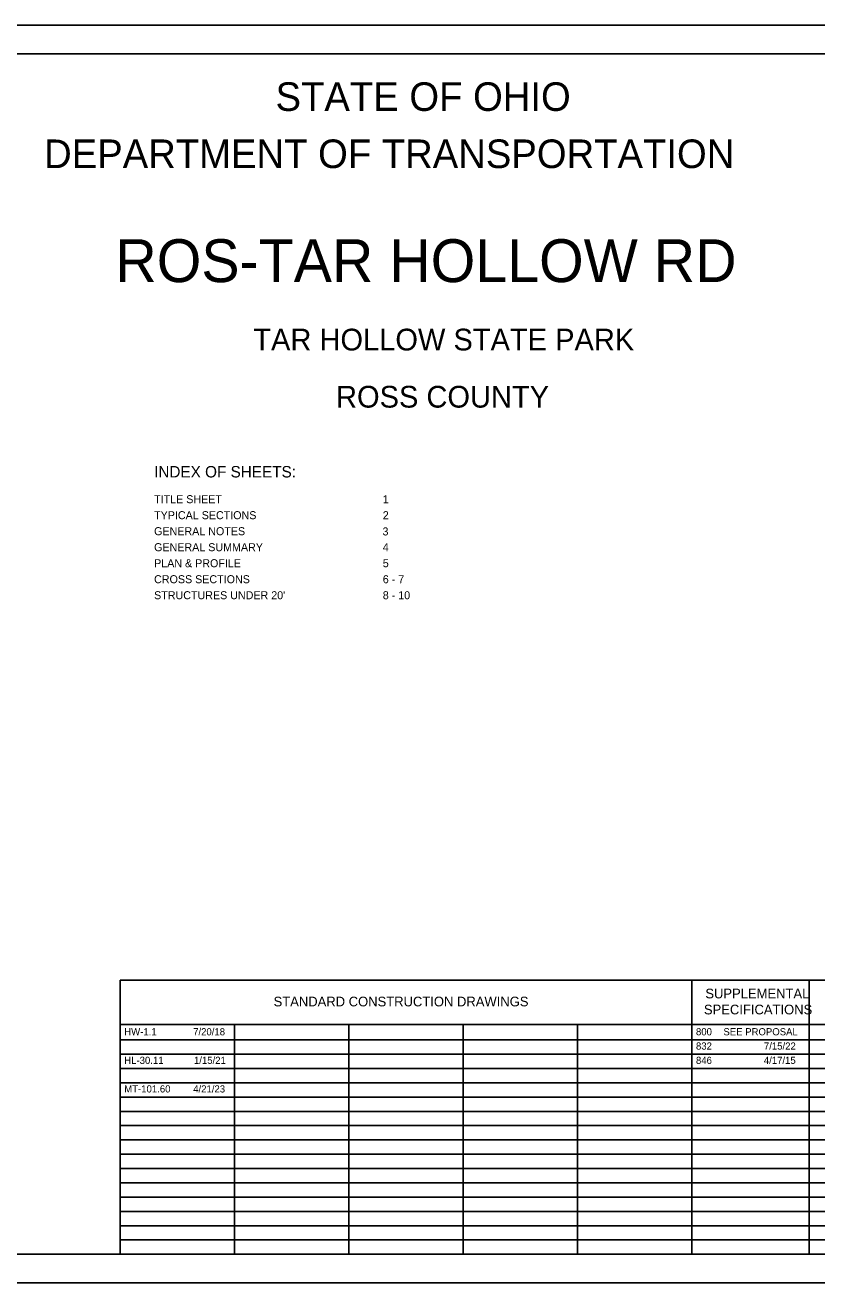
# Model space of a CAD drawing. Extents: x -13.1 to 43.1, y 0 to 22.
# Drawn here: x 9.59 to 23.44, y 0 to 22 of the extents above; entities that cross this region are included whole.
import ezdxf

# ---------------------------------------------------------------- set-up
doc = ezdxf.new("R2010")
doc.units = 0
for name, color, linetype in [('SH_Border', 7, 'Continuous'), ('SH_Data', 7, 'Continuous'), ('SH_Text', 7, 'Continuous')]:
    doc.layers.add(name, color=color, linetype=linetype)

msp = doc.modelspace()

# ---------------------------------------------------------------- linework, layer by layer
at = {"layer": 'SH_Border'}
msp.add_lwpolyline([(1.5, 21.5), (33.5, 21.5), (33.5, 0.5), (1.5, 0.5)], close=True, dxfattribs=at)
at = {"layer": 'SH_Data'}
for p, q in [((11.25, 5.292), (25.025, 5.292)), ((11.25, 0.5), (11.25, 5.292)), ((21.25, 0.5), (21.25, 5.292)), ((23.3, 0.5), (23.3, 5.292)), ((11.25, 4.521), (25.025, 4.521)), ((13.25, 0.5), (13.25, 4.521)), ((15.25, 0.5), (15.25, 4.521)), ((17.25, 0.5), (17.25, 4.521)), ((19.25, 0.5), (19.25, 4.521)), ((11.25, 4.25), (21.25, 4.25)), ((21.25, 4.25), (25.025, 4.25)), ((11.25, 4), (25.025, 4)), ((11.25, 3.75), (25.025, 3.75)), ((11.25, 3.5), (25.025, 3.5)), ((11.25, 3.25), (25.025, 3.25)), ((11.25, 3), (25.025, 3)), ((11.25, 2.75), (25.025, 2.75)), ((11.25, 2.5), (25.025, 2.5)), ((11.25, 2.25), (25.025, 2.25)), ((11.25, 2), (25.025, 2)), ((11.25, 1.75), (25.025, 1.75)), ((11.25, 1.5), (25.025, 1.5)), ((11.25, 1.25), (25.025, 1.25)), ((11.25, 1), (25.025, 1)), ((11.25, 0.75), (25.025, 0.75))]:
    msp.add_line(p, q, dxfattribs=at)
msp.add_lwpolyline([(0, 0), (34, 0), (34, 22), (0, 22)], close=True, dxfattribs=at)

# ---------------------------------------------------------------- texts
at = {"layer": 'SH_Text'}
for s, height, p in [('STATE OF OHIO', 0.5, (13.968, 20.5)), ('DEPARTMENT OF TRANSPORTATION', 0.5, (9.92, 19.5)), ('ROS-TAR HOLLOW RD', 0.75, (11.166, 17.505)), ('TAR HOLLOW STATE PARK', 0.38, (13.579, 16.31)), ('ROSS COUNTY', 0.38, (15.026, 15.31)), ('INDEX OF SHEETS:', 0.2, (11.844, 14.088)), ('TITLE SHEET', 0.14, (11.844, 13.638)), ('1', 0.14, (15.844, 13.638)), ('TYPICAL SECTIONS', 0.14, (11.844, 13.358)), ('2', 0.14, (15.844, 13.358)), ('GENERAL NOTES', 0.14, (11.844, 13.078)), ('3', 0.14, (15.839, 13.074)), ('GENERAL SUMMARY', 0.14, (11.844, 12.798)), ('4', 0.14, (15.844, 12.798)), ('PLAN & PROFILE', 0.14, (11.844, 12.518)), ('5', 0.14, (15.844, 12.518)), ('CROSS SECTIONS', 0.14, (11.844, 12.238)), ('6 - 7', 0.14, (15.844, 12.238)), ("STRUCTURES UNDER 20'", 0.14, (11.844, 11.958)), ('8 - 10', 0.14, (15.844, 11.958)), ('SUPPLEMENTAL', 0.17, (21.486, 4.976)), ('STANDARD CONSTRUCTION DRAWINGS', 0.17, (13.934, 4.836)), ('SPECIFICATIONS', 0.17, (21.461, 4.696)), ('HW-1.1', 0.125, (11.322, 4.33)), ('7/20/18', 0.125, (12.527, 4.33)), ('800', 0.125, (21.322, 4.33)), ('SEE PROPOSAL', 0.125, (21.802, 4.33)), ('832', 0.125, (21.322, 4.08)), ('7/15/22', 0.125, (22.51, 4.08)), ('1/15/21', 0.125, (12.541, 3.83)), ('4/17/15', 0.125, (22.509, 3.83)), ('HL-30.11', 0.125, (11.322, 3.83)), ('846', 0.125, (21.322, 3.83)), ('MT-101.60', 0.125, (11.322, 3.33)), ('4/21/23', 0.125, (12.528, 3.33))]:
    msp.add_text(s, height=height, dxfattribs=at).set_placement(p)

doc.saveas('drawing.dxf')
